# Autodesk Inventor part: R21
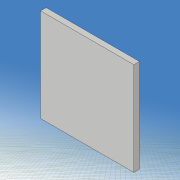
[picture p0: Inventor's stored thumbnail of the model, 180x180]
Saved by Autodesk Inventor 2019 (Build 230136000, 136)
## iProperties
Created: 2021-05
Part Number: R21
Material: 一般
Document SubType Name: Modeling
Designer: kikut
Density: 1 g/cm^3
Appearance: 既定
Mass: 0.0292464 g
Surface Area: 1.16635 cm^2
Volume: 0.0292464 cm^3
Author: kikut
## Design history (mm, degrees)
sketch "スケッチ1"
  geometry: L1 (80, 60)-(-80, 60); L2 (-80, 60)-(-80, -60); L3 (-80, -60)-(80, -60); L4 (80, -60)-(80, 60); L5 (80, 60)-(-80, -60); L6 (-80, 60)-(80, -60); 1 further point
  constraints: 12 end point, 2 midpoint, 2 parallel, 1 horizontal, 1 perpendicular
  dimensions: "d0" = 160 distance of L2.end L3.end; "d1" = 120 distance of L1.end L2.end
extrude "押し出し1" new body sketch "スケッチ1" stored distance "d2" = 0.6; taper "d3" = 0 deg
sketch "スケッチ2"
  geometry: L1 (-140, 0)-(140, 0) reference; L2 (0, -54)-(20, -30); L3 (0, 54)-(20, 30); L4 (0, -3)-(6.514, -3); L5 (6.514, -3)-(16, -6); L6 (16, -6)-(24, -3); L7 (24, -3)-(33.716, -3); L8 (0, 3)-(6.514, 3); L9 (6.514, 3)-(16, 6); L10 (16, 6)-(24, 3); L11 (24, 3)-(33.716, 3); L12 (0, -98)-(0, 98) reference; L13 (-100, -70)-(100, -70); L14 (100, -70)-(100, 70); L15 (100, 70)-(-100, 70); L16 (-100, 70)-(-100, -70); L17 (-100, -70)-(100, 70); L18 (100, -70)-(-100, 70); A1 r 60 centre (54.312, 28.5) between (0, 54) and (0, 3); A2 r 60 centre (54.312, -28.5) between (0, -3) and (0, -54); A3 r 18.111 centre (18, -12) between (20, -30) and (33.716, -3); A4 r 18.111 centre (18, 12) between (33.716, 3) and (20, 30); 1 further point
  constraints: 32 end point, 8 point on circle, 8 symmetric about line, 4 centre point, 3 horizontal, 2 collinear, 2 midpoint, 2 parallel, 1 perpendicular
  dimensions: "d5" = 60 radius of A1; "d6" = 6 distance of L8.start L4.start; "d7" = 108 distance of L3.start L2.start; "d8" = 0 horizontal distance of L3.start L8.start; "d9" = 60 distance of L3.end L2.end; "d10" = 0 horizontal distance of point (0, 0) L3.start; "d11" = 20 horizontal distance of L3.start L3.end; "d12" = 24 distance of A4.centre A3.centre; "d13" = 6 distance of L11.end L7.end; "d14" = 12 distance of L9.end L5.end; "d15" = 16 distance from line of L12 L5.end; "d16" = 24 distance from line of L6.end L12; "d17" = 200 distance of L14.end L15.end; "d18" = 140 distance of L15.end L13.start; "d30" = 18 distance from line of L12 A4.centre
extrude "押し出し2" cut sketch "スケッチ2" stored distance "d19" = 10; taper "d20" = 0 deg
sketch "スケッチ3"
  geometry: L1 (49.705, -17.97)-(33.948, -15.191); L2 (33.948, -15.191)-(34.295, -13.222); L3 (34.295, -13.222)-(50.052, -16); L4 (50.052, -16)-(49.705, -17.97); L5 (49.705, -17.97)-(34.295, -13.222); L6 (33.948, -15.191)-(50.052, -16); L7 (50.052, 16)-(34.295, 13.222); L8 (34.295, 13.222)-(33.948, 15.191); L9 (33.948, 15.191)-(49.705, 17.97); L10 (49.705, 17.97)-(50.052, 16); L11 (50.052, 16)-(33.948, 15.191); L12 (34.295, 13.222)-(49.705, 17.97); L13 (-112, 0)-(112, 0) reference; L14 (0, -84)-(0, 84) reference; 3 further points
  constraints: 24 end point, 4 midpoint, 4 parallel, 2 perpendicular, 2 symmetric about line
  dimensions: "d21" = 2 distance of L3.end L1.start; "d22" = 2 distance of L9.end L7.start; "d23" = 16 distance of L8.end L9.end; "d24" = 42 distance from line of L14 point (42, 15.596); "d26" = 10 deg angle of L7 L13; "d62" = 16 distance from line of L3.end L13
extrude "押し出し3" join sketch "スケッチ3" distance "d27" = 0.6; taper "d28" = 0 deg
fillet "フィレット1" dims "d31" = 2
fillet "フィレット2" dims "d32" = 1
sketch "スケッチ6"
  geometry: L1 (-20, 60)-(80, 60); L2 (80, 60)-(80, -60); L3 (80, -60)-(-20, -60); L4 (-20, -60)-(-20, 60); L5 (-46.168, 0)-(93.832, 0) reference; L6 (0, -84)-(0, 84) reference; L7 (10, 10)-(20, 10); L8 (20, 10)-(20, 20); L9 (20, 20)-(10, 20); L10 (10, 20)-(10, 10); 1 further point
  constraints: 16 end point, 4 parallel, 2 horizontal, 2 perpendicular, 1 other
  dimensions: "d63" = 120 distance of L3.end L1.start; "d64" = 100 distance of L1.start L1.end; "d65" = 20 distance between parallel lines of L6 L4; "d66" = 10 distance of L8.end L9.end; "d73" = 10 distance of L9.end L7.start; "d74" = 10 distance between parallel lines of L7 L5; "d75" = 30 distance between parallel lines of L10 L4
extrude "押し出し4" cut sketch "スケッチ6" stored distance "d70" = 10; taper "d71" = 0 deg
node "ソリッド1"
